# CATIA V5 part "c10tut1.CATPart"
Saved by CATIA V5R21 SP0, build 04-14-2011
Part number: c10tut1
Bounding box of the stored display mesh (mm): x -88.579 to 88.579, y -88.579 to 151.815, z -258.54 to 20
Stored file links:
  D:\CATIA V5R21 E-RESOURCES\CATIA-V5R21\catia-v5r21-prt\c10-catia-v5r20-prt\c10-catia-v5r21-tut01.CATPart
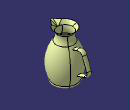
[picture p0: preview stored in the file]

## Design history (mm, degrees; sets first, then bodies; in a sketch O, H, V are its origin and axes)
Body1 (main body)
  Sketch1 on xy-plane, origin (0, 0, 0), H (1, 0, 0), V (0, 1, 0)
    circle A1 centre (0, 0) radius 45
    point P1 (-5, -44.7214)
    point P2 (5, -44.7214)
    radius A1 = 45
    distance P2 P1 = 10
    distance V P1 = 5
    coincidence: P1 A1, P2 A1
  Plane1: type Offset, RefPlane xy-plane, Offset 20
  Sketch2 on Plane1, origin (0, 0, 20), H (1, 0, 0), V (0, 1, 0)
    arc A1 centre (0, 0) radius 60 from (30.5123, -51.6623) to (-30.5123, -51.6623) ccw
    line L1 (-30.5123, -51.6623) -> (-7.9335, -81.0876)
    point P1 (0, -91.4268)
    line L2 (7.9335, -81.0876) -> (30.5123, -51.6623)
    arc A2 centre (0, -75) radius 10 from (-7.9335, -81.0876) to (7.9335, -81.0876) ccw
    point P4 (0, -75)
    radius A1 = 60
    angle L1 L2 = 75
    radius A2 = 10
    distance P4 H = 75
    coincidence: P1 V, L1 P1, L2 P1, P4 V
    tangency: A2 L1, A2 L2
  Line1: type PtPt, FirstPoint Sketch1.P2, SecondPoint vertex [element of Sketch2 | element of Sketch2]
  Loft1: Sections (Sketch1.A1; Sketch2), Guides Line1
  Sketch3 on yz-plane, origin (0, 0, 0), H (0, 1, 0), V (0, 0, 1)
    axis line L1 (0, 49.2285) -> (0, -442.7765)
    point P1 (0, 49.2285)
    arc A1 centre (-106.3963, -163.4174) radius 195 from (70, -246.5398) to (52.2275, -50) ccw
    point P4 (70, -246.5398)
    point P5 (52.2275, -50)
    arc A2 centre (96.9675, -18.0105) radius 55 from (45, 0) to (52.2275, -50) ccw
    point P7 (52.2275, -50)
    point P8 (45, 0)
    line L2 (54, -258.5398) -> (64, -258.5398)
    point P9 (54, -258.5398)
    point P10 (64, -258.5398)
    arc A3 centre (64, -251.0398) radius 7.5 from (64, -258.5398) to (70, -246.5398) ccw
    point P12 (64, -258.5398)
    arc A4 centre (0, -425) radius 175 from (54, -258.5398) to (0, -250) ccw
    point P13 (0, -425)
    point P14 (0, -250)
    radius A2 = 55
    radius A1 = 195
    radius A3 = 7.5
    length L2 = 10
    radius A4 = 175
    distance P14 H = 250
    "Radius" P4 L1 = 70
    "Radius" P9 L1 = 54
    "Radius" P8 L1 = 45
    distance P5 H = 50
    coincidence: P1 V, P7 A1, P7 P5, P10 P12, P13 L1, P14 L1, P8 H
    tangency: A2 A1, A3 L2
    vertical: L1 V
    horizontal: L2 H
  Revol1: Element1 Sketch3, Angle1 360
  Sketch4 on yz-plane, origin (0, 0, 0), H (0, 1, 0), V (0, 0, 1)
    point P1 (35.2741, -74.8693)
    line L1 (35.2741, -74.8693) -> (86.9572, -56.0582)
    line L2 (119, -71) -> (145.5066, -143.8262)
    line L3 (130.5647, -175.869) -> (63.8466, -200.1524)
    arc A1 centre (95.5077, -79.5505) radius 25 from (86.9572, -56.0582) to (119, -71) cw
    point P4 (119, -71)
    arc A2 centre (122.0142, -152.3767) radius 25 from (145.5066, -143.8262) to (130.5647, -175.869) cw
    radius A1 = 25
    radius A2 = 25
    length L2 = 77.5
    length L1 = 55
    angle H L1 = 20
    distance P4 V = 119
    distance P4 H = 71
    length L3 = 71
    perpendicularity: L2 L1
    parallelism: L3 L1
    tangency: A1 L1, A1 L2, A2 L2, A2 L3
  Plane2: type Normal, Curve Sketch4, RefPoint Sketch4.P1
  Sketch5 on Plane2, origin (0, 7.0853, 2.5788), H (1, 0, 0), V (0, -0.342, 0.9397)
    point P1 (0, -82.4186)
    ellipse A1 centre (0, -82.4186) semi-axes 12.5, 5 rotation 0
    reference projected point E1 (0, -82.4186) from Sketch4.P1
    "Radius" A1 = 5
    "Radius" A1 = 12.5
    horizontal: A1 H
    coincidence: P1 E1
  Sweep1: type Unspec, Profile Sketch5, Guide Sketch4
  Split1: ToCut Sweep1, Cutting Revol1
